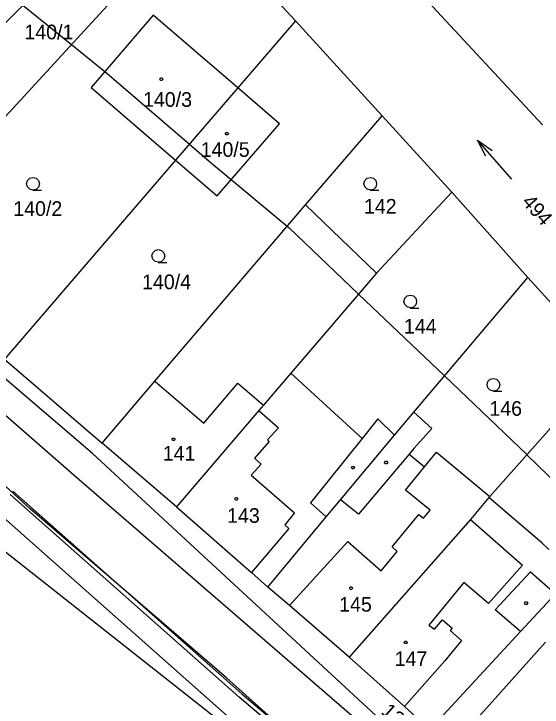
# Model space of a CAD drawing. Extents: x -755359 to -754474, y -1162585 to -1161655.
# Drawn here: x -754933.3 to -754872, y -1161780.5 to -1161700.1 of the extents above; entities that cross this region are included whole.
import ezdxf

# ---------------------------------------------------------------- set-up
doc = ezdxf.new("R2010")
doc.units = 0
for name, color, linetype in [('Vrstva 1', 7, 'Continuous'), ('Vrstva 11', 7, 'Continuous'), ('Vrstva 12', 7, 'Continuous'), ('Vrstva 13', 7, 'Continuous'), ('Vrstva 2', 7, 'Continuous'), ('Vrstva 3', 7, 'Continuous'), ('Vrstva 4', 7, 'Continuous'), ('Vrstva 5', 7, 'Continuous')]:
    doc.layers.add(name, color=color, linetype=linetype)

msp = doc.modelspace()

# ---------------------------------------------------------------- linework, layer by layer
at = {"layer": 'Vrstva 1'}
for p, q in [((-754871.95, -1161713.02), (-754913.71, -1161667.99)), ((-754937.15, -1161704.08), (-754916.55, -1161683.55)), ((-754948.77, -1161727.83), (-754912.31, -1161688.18)), ((-754912.31, -1161688.18), (-754900.61, -1161700.97)), ((-754917.11, -1161700.29), (-754924.29, -1161708.7)), ((-754907.29, -1161708.74), (-754917.11, -1161700.29)), ((-754900.61, -1161700.97), (-754907.29, -1161708.74)), ((-754900.61, -1161700.97), (-754890.53, -1161711.98)), ((-754924.29, -1161708.7), (-754914.5, -1161717.12)), ((-754907.29, -1161708.74), (-754914.5, -1161717.12)), ((-754902.46, -1161712.89), (-754907.29, -1161708.74)), ((-754899.44, -1161722.28), (-754890.53, -1161711.98)), ((-754890.53, -1161711.98), (-754882.46, -1161720.82)), ((-754909.68, -1161721.27), (-754902.46, -1161712.89)), ((-754914.5, -1161717.12), (-754934.36, -1161740.2)), ((-754914.5, -1161717.12), (-754909.68, -1161721.27)), ((-754924.16, -1161751.14), (-754961.05, -1161719.56)), ((-754891.18, -1161730.2), (-754882.46, -1161720.82)), ((-754882.46, -1161720.82), (-754873.65, -1161730.71)), ((-754916.92, -1161742.76), (-754899.44, -1161722.28)), ((-754899.44, -1161722.28), (-754891.18, -1161730.2)), ((-754891.18, -1161730.2), (-754901.13, -1161741.83)), ((-754886.86, -1161746.34), (-754873.65, -1161730.71)), ((-754873.65, -1161730.71), (-754864.46, -1161740.82)), ((-754934.36, -1161740.2), (-754923.04, -1161749.93)), ((-754878.05, -1161756.11), (-754864.46, -1161740.82)), ((-754953.69, -1161741.58), (-754855.01, -1161828.87)), ((-754901.13, -1161741.83), (-754904.31, -1161745.54)), ((-754892.85, -1161749.38), (-754901.13, -1161741.83)), ((-754923.04, -1161749.93), (-754916.92, -1161742.76)), ((-754904.31, -1161745.54), (-754904.83, -1161746.15)), ((-754904.83, -1161746.15), (-754914.4, -1161757.3)), ((-754889.1, -1161749.01), (-754886.86, -1161746.34)), ((-754886.86, -1161746.34), (-754884.77, -1161748.25)), ((-754891.04, -1161747.13), (-754892.85, -1161749.38)), ((-754889.1, -1161749.01), (-754891.04, -1161747.13)), ((-754884.77, -1161748.25), (-754886.86, -1161750.54)), ((-754895.36, -1161756.49), (-754889.1, -1161749.01)), ((-754914.4, -1161757.3), (-754923.04, -1161749.93)), ((-754883.24, -1161788.9), (-754924.16, -1161751.14)), ((-754886.86, -1161750.54), (-754887.42, -1161751.2)), ((-754885.63, -1161752.68), (-754884.25, -1161750.98)), ((-754884.25, -1161750.98), (-754878.05, -1161756.11)), ((-754887.42, -1161751.2), (-754885.63, -1161752.68)), ((-754897.02, -1161758.47), (-754895.36, -1161756.49)), ((-754878.16, -1161756.23), (-754880.31, -1161758.79)), ((-754878.16, -1161756.23), (-754878.05, -1161756.11)), ((-754872.01, -1161761.48), (-754878.16, -1161756.23)), ((-754914.4, -1161757.3), (-754905.7, -1161764.94)), ((-754903.79, -1161766.62), (-754897.02, -1161758.47)), ((-754880.31, -1161758.79), (-754894.38, -1161774.75)), ((-754871.19, -1161762.26), (-754872.01, -1161761.48)), ((-754905.7, -1161764.94), (-754903.79, -1161766.62)), ((-754901.28, -1161768.76), (-754903.79, -1161766.62)), ((-754874.49, -1161771.77), (-754870.43, -1161767.39)), ((-754894.38, -1161774.75), (-754901.28, -1161768.76)), ((-754885, -1161783.11), (-754874.49, -1161771.77)), ((-754882.65, -1161785.33), (-754871.6, -1161773.02)), ((-754887.95, -1161780.48), (-754894.38, -1161774.75)), ((-754887.95, -1161780.48), (-754885, -1161783.11))]:
    msp.add_line(p, q, dxfattribs=at)
at = {"layer": 'Vrstva 11'}
for p, q in [((-754932.21, -1161699.15), (-754926.59, -1161703.71)), ((-754926.59, -1161703.71), (-754922.71, -1161706.85)), ((-754922.71, -1161706.85), (-754921.93, -1161707.49)), ((-754921.93, -1161707.49), (-754912.9, -1161715.26)), ((-754912.9, -1161715.26), (-754910.33, -1161717.48)), ((-754910.33, -1161717.48), (-754908.05, -1161719.37)), ((-754908.05, -1161719.37), (-754901.56, -1161724.76)), ((-754901.56, -1161724.76), (-754901.31, -1161724.97)), ((-754901.31, -1161724.97), (-754893.27, -1161732.64)), ((-754893.27, -1161732.64), (-754883.31, -1161742.14)), ((-754883.31, -1161742.14), (-754873.77, -1161751.25)), ((-754951.65, -1161748.83), (-754905.2, -1161785.42)), ((-754873.77, -1161751.25), (-754873.75, -1161751.27)), ((-754873.75, -1161751.27), (-754864.21, -1161760.65))]:
    msp.add_line(p, q, dxfattribs=at)
at = {"layer": 'Vrstva 12'}
for p, q in [((-754917.11, -1161700.29), (-754924.29, -1161708.7)), ((-754907.29, -1161708.74), (-754917.11, -1161700.29)), ((-754924.29, -1161708.7), (-754914.5, -1161717.12)), ((-754907.29, -1161708.74), (-754914.5, -1161717.12)), ((-754907.29, -1161708.74), (-754914.5, -1161717.12)), ((-754902.46, -1161712.89), (-754907.29, -1161708.74)), ((-754909.68, -1161721.27), (-754902.46, -1161712.89)), ((-754914.5, -1161717.12), (-754909.68, -1161721.27)), ((-754923.04, -1161749.93), (-754916.92, -1161742.76)), ((-754916.92, -1161742.76), (-754911.23, -1161747.61)), ((-754911.23, -1161747.61), (-754907.28, -1161742.98)), ((-754907.28, -1161742.98), (-754904.31, -1161745.54)), ((-754904.31, -1161745.54), (-754904.83, -1161746.15)), ((-754904.83, -1161746.15), (-754914.4, -1161757.3)), ((-754904.83, -1161746.15), (-754914.4, -1161757.3)), ((-754904.83, -1161746.15), (-754902.55, -1161748.16)), ((-754902.55, -1161748.16), (-754903.86, -1161749.56)), ((-754903.86, -1161749.56), (-754903.65, -1161749.75)), ((-754914.4, -1161757.3), (-754923.04, -1161749.93)), ((-754903.65, -1161749.75), (-754905.34, -1161751.69)), ((-754885.63, -1161752.68), (-754884.25, -1161750.98)), ((-754884.25, -1161750.98), (-754878.05, -1161756.11)), ((-754905.34, -1161751.69), (-754904.59, -1161752.36)), ((-754904.59, -1161752.36), (-754905.74, -1161753.65)), ((-754887.85, -1161755.4), (-754885.63, -1161752.68)), ((-754905.74, -1161753.65), (-754900.72, -1161758.01)), ((-754884.97, -1161757.71), (-754887.85, -1161755.4)), ((-754878.16, -1161756.23), (-754880.31, -1161758.79)), ((-754878.16, -1161756.23), (-754878.05, -1161756.11)), ((-754914.4, -1161757.3), (-754905.7, -1161764.94)), ((-754900.72, -1161758.01), (-754901.83, -1161759.41)), ((-754889.37, -1161761.96), (-754886.28, -1161758.2)), ((-754886.28, -1161758.2), (-754885.74, -1161758.64)), ((-754885.74, -1161758.64), (-754884.97, -1161757.71)), ((-754880.31, -1161758.79), (-754894.38, -1161774.75)), ((-754880.31, -1161758.79), (-754894.38, -1161774.75)), ((-754880.31, -1161758.79), (-754874.27, -1161764.07)), ((-754901.36, -1161759.83), (-754905.7, -1161764.94)), ((-754901.83, -1161759.41), (-754901.36, -1161759.83)), ((-754901.28, -1161768.76), (-754894.51, -1161761.35)), ((-754894.51, -1161761.35), (-754890.67, -1161764.72)), ((-754888.78, -1161762.51), (-754889.37, -1161761.96)), ((-754890.67, -1161764.72), (-754888.78, -1161762.51)), ((-754874.27, -1161764.07), (-754878.21, -1161768.52)), ((-754881.06, -1161766.09), (-754885.13, -1161771.03)), ((-754878.21, -1161768.52), (-754881.06, -1161766.09)), ((-754894.38, -1161774.75), (-754901.28, -1161768.76)), ((-754884.48, -1161771.51), (-754883.53, -1161770.42)), ((-754883.53, -1161770.42), (-754882.41, -1161771.4)), ((-754885.13, -1161771.03), (-754884.48, -1161771.51)), ((-754882.41, -1161771.4), (-754882.64, -1161771.67)), ((-754882.64, -1161771.67), (-754881.34, -1161772.8)), ((-754881.34, -1161772.8), (-754883.28, -1161775.18)), ((-754887.95, -1161780.48), (-754894.38, -1161774.75)), ((-754883.28, -1161775.18), (-754887.95, -1161780.48))]:
    msp.add_line(p, q, dxfattribs=at)
at = {"layer": 'Vrstva 13'}
for p, q in [((-754907.13, -1161779.39), (-754933.69, -1161755.9)), ((-754933.37, -1161755.51), (-754906.81, -1161779.01)), ((-754906.81, -1161779.01), (-754898.61, -1161785.93)), ((-754898.93, -1161786.31), (-754907.13, -1161779.39))]:
    msp.add_line(p, q, dxfattribs=at)
at = {"layer": 'Vrstva 3'}
msp.add_line((-754875.492, -1161719.307), (-754879.468, -1161714.813), dxfattribs=at)
for points in [[(-754878.517, -1161716.642), (-754879.468, -1161714.813), (-754877.768, -1161715.98)], [(-754931.04, -1161720.59), (-754931.42, -1161720.49), (-754931.69, -1161720.22), (-754931.79, -1161719.85), (-754931.69, -1161719.48), (-754931.42, -1161719.21), (-754931.05, -1161719.11), (-754930.68, -1161719.21), (-754930.41, -1161719.48), (-754930.31, -1161719.86), (-754930.41, -1161720.24), (-754930.68, -1161720.51), (-754931.06, -1161720.61), (-754930.06, -1161720.61)], [(-754891.91, -1161720.59), (-754892.29, -1161720.49), (-754892.56, -1161720.22), (-754892.66, -1161719.85), (-754892.56, -1161719.48), (-754892.29, -1161719.21), (-754891.92, -1161719.11), (-754891.55, -1161719.21), (-754891.28, -1161719.48), (-754891.18, -1161719.86), (-754891.28, -1161720.24), (-754891.55, -1161720.51), (-754891.93, -1161720.61), (-754890.93, -1161720.61)], [(-754916.5, -1161728.96), (-754916.88, -1161728.86), (-754917.15, -1161728.59), (-754917.25, -1161728.22), (-754917.15, -1161727.85), (-754916.88, -1161727.58), (-754916.51, -1161727.48), (-754916.14, -1161727.58), (-754915.87, -1161727.85), (-754915.77, -1161728.23), (-754915.87, -1161728.61), (-754916.14, -1161728.88), (-754916.52, -1161728.98), (-754915.52, -1161728.98)], [(-754887.27, -1161734.24), (-754887.65, -1161734.14), (-754887.92, -1161733.87), (-754888.02, -1161733.5), (-754887.92, -1161733.13), (-754887.65, -1161732.86), (-754887.28, -1161732.76), (-754886.91, -1161732.86), (-754886.64, -1161733.13), (-754886.54, -1161733.51), (-754886.64, -1161733.89), (-754886.91, -1161734.16), (-754887.29, -1161734.26), (-754886.29, -1161734.26)], [(-754877.62, -1161743.9), (-754878, -1161743.8), (-754878.27, -1161743.53), (-754878.37, -1161743.16), (-754878.27, -1161742.79), (-754878, -1161742.52), (-754877.63, -1161742.42), (-754877.26, -1161742.52), (-754876.99, -1161742.79), (-754876.89, -1161743.17), (-754876.99, -1161743.55), (-754877.26, -1161743.82), (-754877.64, -1161743.92), (-754876.64, -1161743.92)]]:
    msp.add_lwpolyline(points, dxfattribs=at)
at = {"layer": 'Vrstva 4'}
for p, q in [((-754931.36, -1161757.54), (-754960.25, -1161731.5)), ((-754943.25, -1161738.89), (-754926.26, -1161753.63)), ((-754916.92, -1161742.76), (-754911.23, -1161747.61)), ((-754911.23, -1161747.61), (-754907.28, -1161742.98)), ((-754907.28, -1161742.98), (-754904.31, -1161745.54)), ((-754904.83, -1161746.15), (-754902.55, -1161748.16)), ((-754902.55, -1161748.16), (-754903.86, -1161749.56)), ((-754903.86, -1161749.56), (-754903.65, -1161749.75)), ((-754892.85, -1161749.38), (-754898.87, -1161756.86)), ((-754903.65, -1161749.75), (-754905.34, -1161751.69)), ((-754905.34, -1161751.69), (-754904.59, -1161752.36)), ((-754887.42, -1161751.2), (-754893.29, -1161758.15)), ((-754904.59, -1161752.36), (-754905.74, -1161753.65)), ((-754887.85, -1161755.4), (-754885.63, -1161752.68)), ((-754926.26, -1161753.63), (-754883.79, -1161790.36)), ((-754905.74, -1161753.65), (-754900.72, -1161758.01)), ((-754884.97, -1161757.71), (-754887.85, -1161755.4)), ((-754893.29, -1161758.15), (-754895.36, -1161756.49)), ((-754908.58, -1161777.13), (-754931.36, -1161757.54)), ((-754898.87, -1161756.86), (-754897.02, -1161758.47)), ((-754900.72, -1161758.01), (-754901.83, -1161759.41)), ((-754889.37, -1161761.96), (-754886.28, -1161758.2)), ((-754886.28, -1161758.2), (-754885.74, -1161758.64)), ((-754885.74, -1161758.64), (-754884.97, -1161757.71)), ((-754880.31, -1161758.79), (-754874.27, -1161764.07)), ((-754901.36, -1161759.83), (-754905.7, -1161764.94)), ((-754901.83, -1161759.41), (-754901.36, -1161759.83)), ((-754901.28, -1161768.76), (-754894.51, -1161761.35)), ((-754894.51, -1161761.35), (-754890.67, -1161764.72)), ((-754888.78, -1161762.51), (-754889.37, -1161761.96)), ((-754890.67, -1161764.72), (-754888.78, -1161762.51)), ((-754874.27, -1161764.07), (-754878.21, -1161768.52)), ((-754877.44, -1161769.25), (-754873.32, -1161764.86)), ((-754873.32, -1161764.86), (-754870.43, -1161767.39)), ((-754881.06, -1161766.09), (-754885.13, -1161771.03)), ((-754878.21, -1161768.52), (-754881.06, -1161766.09)), ((-754874.49, -1161771.77), (-754877.44, -1161769.25)), ((-754884.48, -1161771.51), (-754883.53, -1161770.42)), ((-754883.53, -1161770.42), (-754882.41, -1161771.4)), ((-754885.13, -1161771.03), (-754884.48, -1161771.51)), ((-754882.41, -1161771.4), (-754882.64, -1161771.67)), ((-754882.64, -1161771.67), (-754881.34, -1161772.8)), ((-754881.34, -1161772.8), (-754883.28, -1161775.18)), ((-754883.28, -1161775.18), (-754887.95, -1161780.48)), ((-754888.68, -1161795.04), (-754908.58, -1161777.13))]:
    msp.add_line(p, q, dxfattribs=at)
at = {"layer": 'Vrstva 5'}
for points in [[(-754916.07, -1161707.56), (-754915.98, -1161707.71), (-754916.07, -1161707.86), (-754916.25, -1161707.86), (-754916.34, -1161707.71), (-754916.25, -1161707.56)], [(-754908.47, -1161713.89), (-754908.38, -1161714.04), (-754908.47, -1161714.19), (-754908.65, -1161714.19), (-754908.74, -1161714.04), (-754908.65, -1161713.89)], [(-754914.66, -1161749.34), (-754914.57, -1161749.49), (-754914.66, -1161749.64), (-754914.84, -1161749.64), (-754914.93, -1161749.49), (-754914.84, -1161749.34)], [(-754893.84, -1161752.62), (-754893.75, -1161752.77), (-754893.84, -1161752.92), (-754894.02, -1161752.92), (-754894.11, -1161752.77), (-754894.02, -1161752.62)], [(-754889.99, -1161752.02), (-754889.9, -1161752.17), (-754889.99, -1161752.32), (-754890.17, -1161752.32), (-754890.26, -1161752.17), (-754890.17, -1161752.02)], [(-754907.36, -1161756.25), (-754907.27, -1161756.4), (-754907.36, -1161756.55), (-754907.54, -1161756.55), (-754907.63, -1161756.4), (-754907.54, -1161756.25)], [(-754894.07, -1161766.6), (-754893.98, -1161766.75), (-754894.07, -1161766.9), (-754894.25, -1161766.9), (-754894.34, -1161766.75), (-754894.25, -1161766.6)], [(-754873.74, -1161768.34), (-754873.65, -1161768.49), (-754873.74, -1161768.64), (-754873.92, -1161768.64), (-754874.01, -1161768.49), (-754873.92, -1161768.34)], [(-754887.72, -1161772.88), (-754887.63, -1161773.03), (-754887.72, -1161773.18), (-754887.9, -1161773.18), (-754887.99, -1161773.03), (-754887.9, -1161772.88)]]:
    msp.add_lwpolyline(points, close=True, dxfattribs=at)

# ---------------------------------------------------------------- texts
at = {"layer": 'Vrstva 2'}
for s, p in [('140/1', (-754932.047, -1161703.1)), ('140/3', (-754918.287, -1161710.93)), ('140/5', (-754911.597, -1161716.73)), ('140/2', (-754933.337, -1161723.58)), ('142', (-754892.657, -1161723.32)), ('140/4', (-754918.397, -1161732.08)), ('144', (-754888.017, -1161737.23)), ('146', (-754878.107, -1161746.76)), ('141', (-754915.997, -1161751.96)), ('143', (-754908.527, -1161759.17)), ('145', (-754895.527, -1161769.47)), ('147', (-754889.097, -1161775.78))]:
    msp.add_text(s, height=1.7, dxfattribs=at).set_placement(p)
for s, rotation, p in [('494', 311.40256, (-754874.423, -1161722.018)), ('125/1', 318.62183, (-754890.765, -1161781.21))]:
    msp.add_text(s, height=1.7, rotation=rotation, dxfattribs=at).set_placement(p)

doc.saveas('drawing.dxf')
